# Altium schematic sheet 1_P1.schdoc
size 302 x 215 mm; Symbol: Sheet_A4; Device: Sheet_A4; @Project Name: Sheet_1; Company: YuzukiHD; Version: 1.0; @Page No: 1; @Page Count: 1; @Update Date: 2024-07-06 22:09:21; Comment: GloomyGhost
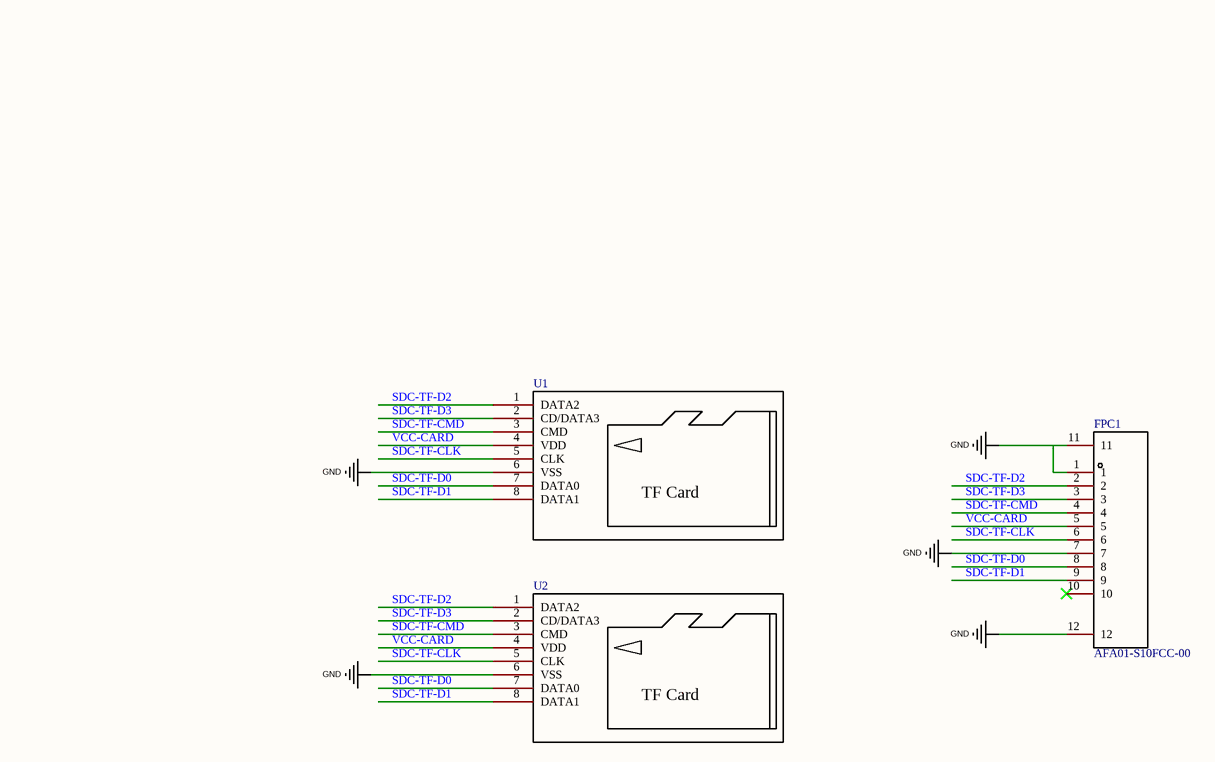
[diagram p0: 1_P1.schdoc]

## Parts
FPC1  AFA01-S10FCC-00  [FPC-SMD_AFA01-S10FCC-00]
U1  TF Shape  [SD卡]  (value not drawn)
U2  TF Shape  [SD卡]  (value not drawn)

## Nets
GND: FPC1.1 FPC1.7 FPC1.11 FPC1.12 U1.6(VSS) U2.6(VSS)
SDC-TF-CLK: FPC1.6 U1.5(CLK) U2.5(CLK)
SDC-TF-CMD: FPC1.4 U1.3(CMD) U2.3(CMD)
SDC-TF-D0: FPC1.8 U1.7(DATA0) U2.7(DATA0)
SDC-TF-D1: FPC1.9 U1.8(DATA1) U2.8(DATA1)
SDC-TF-D2: FPC1.2 U1.1(DATA2) U2.1(DATA2)
SDC-TF-D3: FPC1.3 U1.2(CD/DATA3) U2.2(CD/DATA3)
VCC-CARD: FPC1.5 U1.4(VDD) U2.4(VDD)

Not connected (* = marked no-connect by the designer): FPC1 10*

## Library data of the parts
FPC1 = AFA01-S10FCC-00: 锁定特性:翻盖式;触点类型:下接;触点数量:10P;间距:1mm;安装类型:卧贴;; Manufacturer: JS(钜硕电子); Add into BOM: yes; Locking Feature: 翻盖式; Number of Contacts: 10P; Pitch: 1mm; FFC, FCB Thickness: 0.3mm
U1 U2 = TF Shape: Add into BOM: yes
